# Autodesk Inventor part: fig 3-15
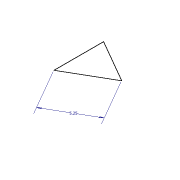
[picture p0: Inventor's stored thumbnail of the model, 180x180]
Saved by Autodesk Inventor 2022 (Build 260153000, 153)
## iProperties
Created: 2009-11
Part Number: fig 3-15
Document SubType Name: Modeling
Designer: Sham
Density: 1 g/cm^3
Material: Generic
Appearance: Default
Author: Sham
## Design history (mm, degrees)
sketch "Sketch1"
  geometry: L1 (0.077, -0.115)-(0.077, -5.365); L2 (0.077, -5.365)-(4.624, -2.74); L3 (4.624, -2.74)-(0.077, -0.115)
  constraints: 6 end point, 2 equal length, 1 vertical
  dimensions: "d1" = 5.25 dimension on L1.start L1.end L1 L2.end L2 L3; "d1" = 5.25 distance of L1.end L2.end
